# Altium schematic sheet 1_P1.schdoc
size 358 x 309 mm; Symbol: Drawing-Symbol_A4; Device: Drawing-Symbol_A4; @Project Name: esp32_c3_ppm_11_11_2025; @Page Count: 1; @Update Date: 2025-12-08; @Create Date: 2025-12-07; @Schematic Name: Schematic1; @Page No: 1; @Page Name: P1; Company: EasyEDA.com; Version: V1.0; Page Size: A4; @Create Time: 21:49:59; @Update Time: 15:23:27; Width: 1377.9527559055118; Height: 1181.1023622047244; Region Start: 1; X Region Count: 6; Y Region Count: 4; Blade Width: 10; Title Block Position: 3; @Board Name: Board1
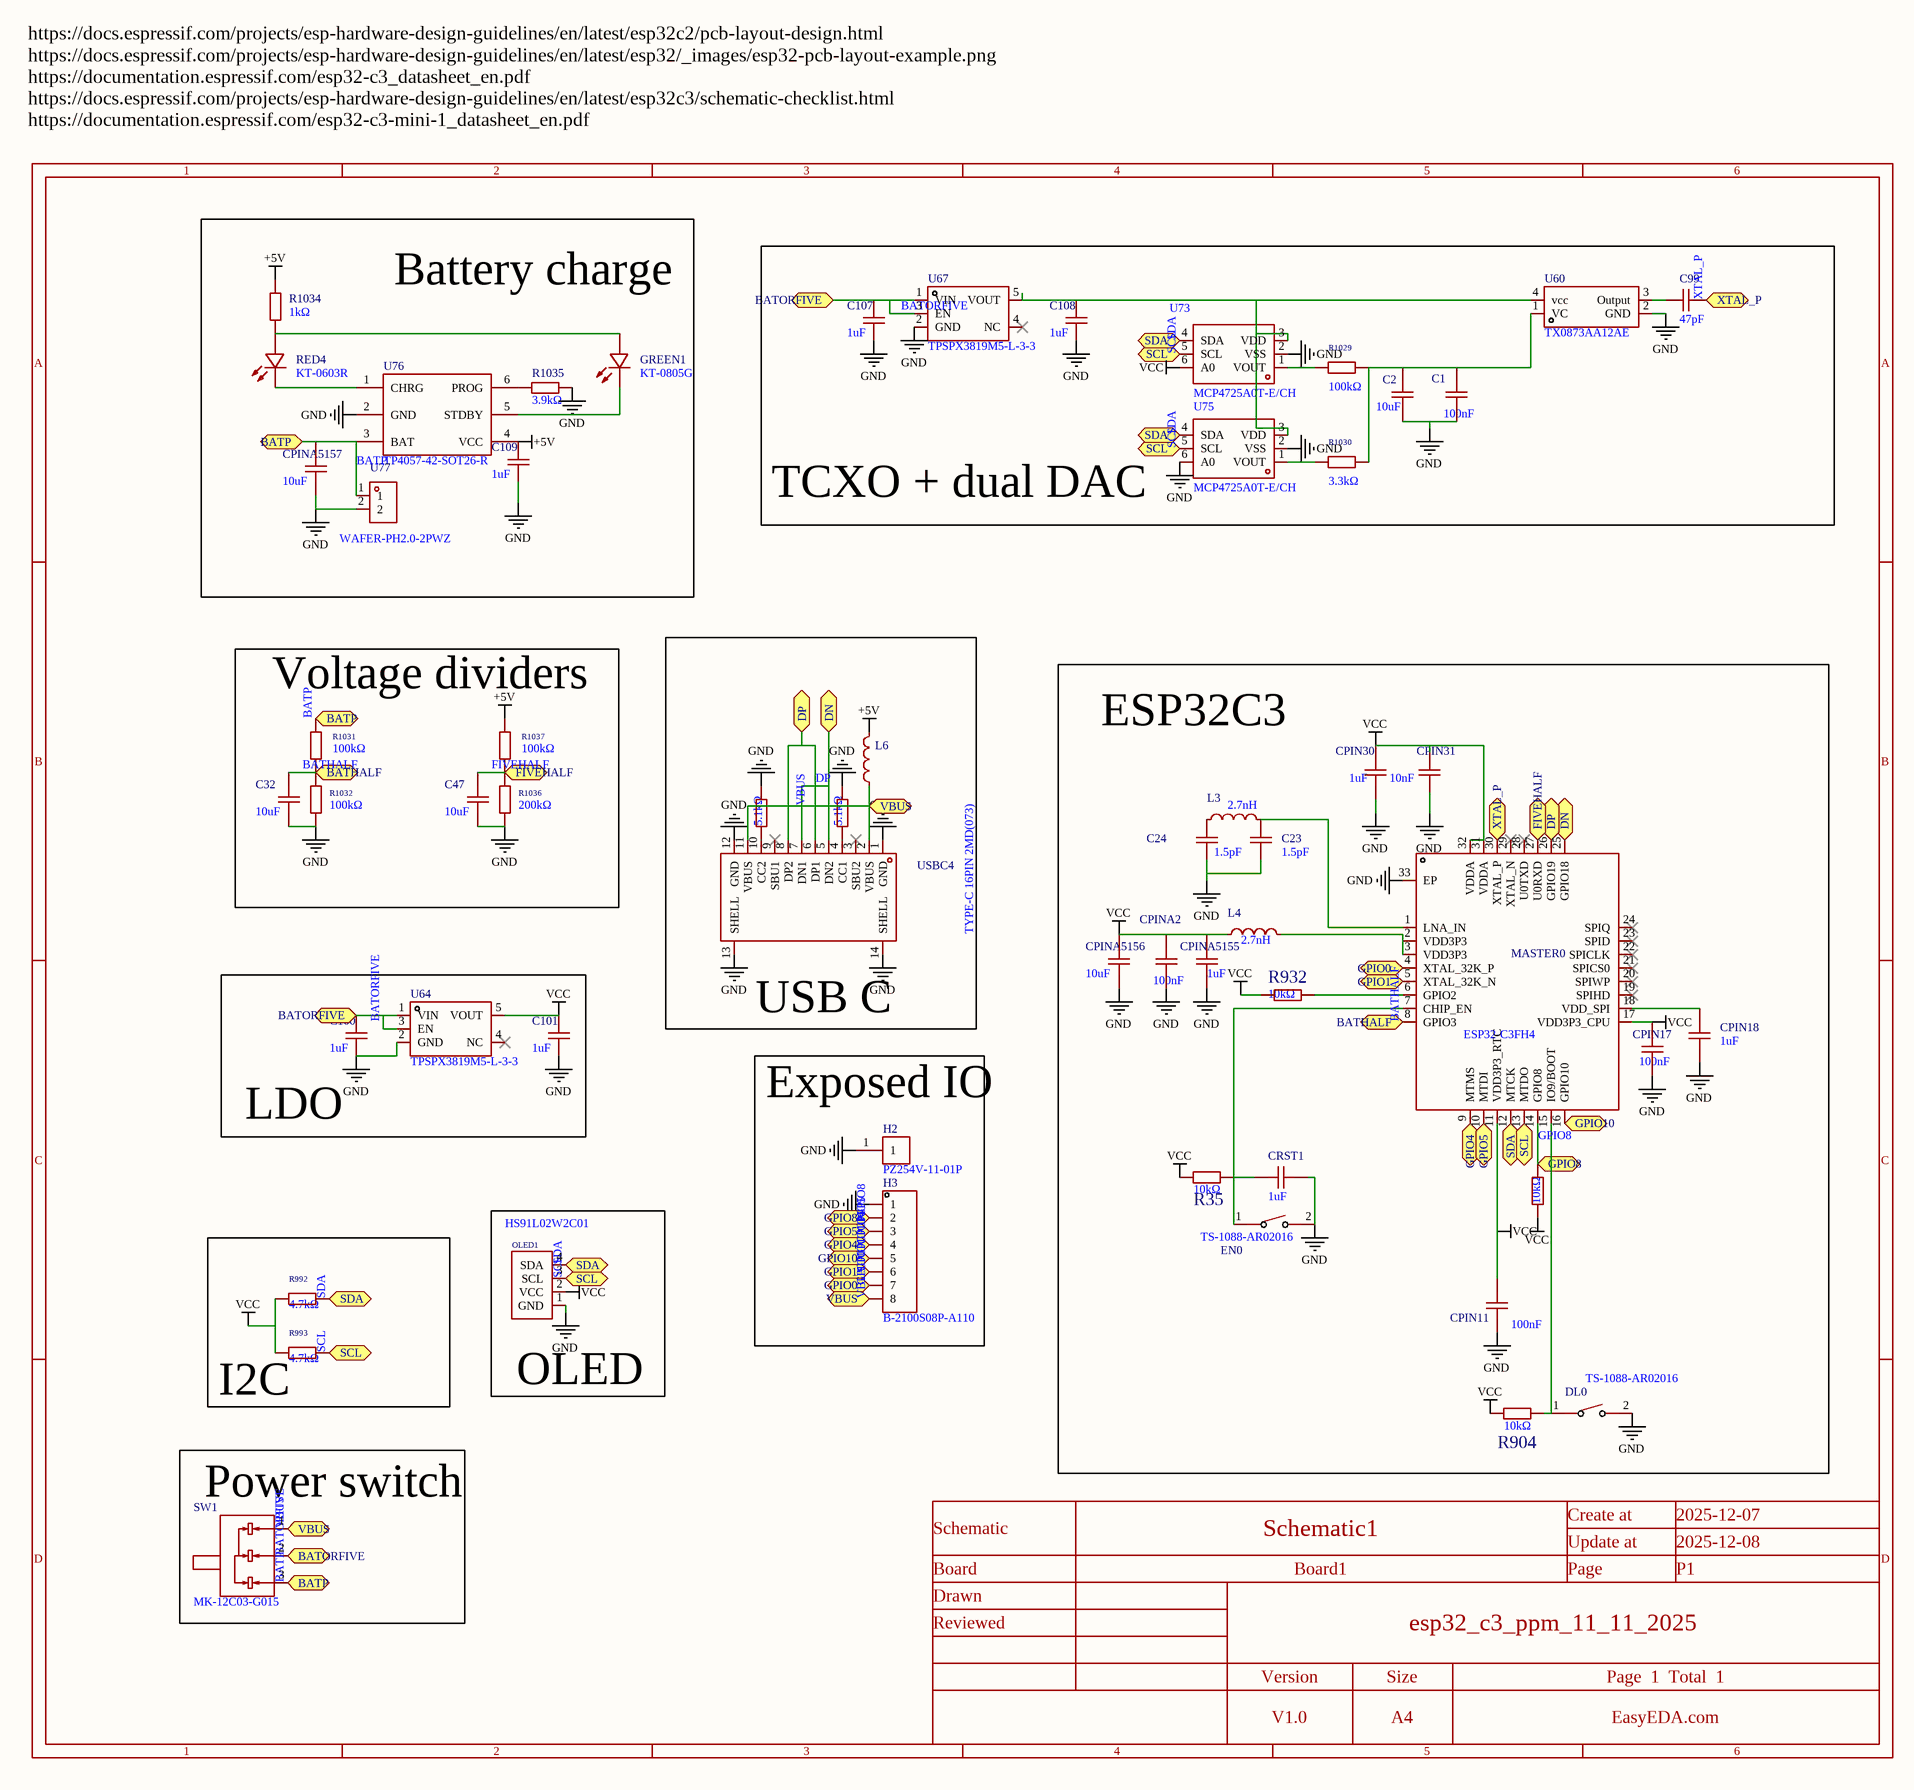
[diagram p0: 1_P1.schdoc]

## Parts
C1  100nF  [C0402]
C2  10uF  [C0402]
C23  1.5pF  [C0402]
C24  1.5pF  [C0402]
C32  10uF  [C0402]
C47  10uF  [C0402]
C99  47pF  [C0402]
C100  1uF  [C0402]
C101  1uF  [C0402]
C107  1uF  [C0402]
C108  1uF  [C0402]
C109  1uF  [C0402]
CPIN11  100nF  [C0402]
CPIN17  100nF  [C0402]
CPIN18  1uF  [C0402]
CPIN30  1uF  [C0402]
CPIN31  10nF  [C0402]
CPINA2  100nF  [C0402]
CPINA5155  1uF  [C0402]
CPINA5156  10uF  [C0402]
CPINA5157  10uF  [C0402]
CRST1  1uF  [C0402]
DL0  TS-1088-AR02016  [SW-SMD_L3.9-W3.0-P4.45]
EN0  TS-1088-AR02016  [SW-SMD_L3.9-W3.0-P4.45]
GREEN1  KT-0805G  [LED0805-R-RD]
H2  PZ254V-11-01P  [HDR-TH_1P-P2.54-V-M]
H3  B-2100S08P-A110  [HDR-TH_8P-P2.54-V-M]
L3  2.7nH  [L0402]
L4  2.7nH  [L0402]
L6  BLM18PG121SN1D  [L0603]  (value not drawn)
MASTER0  ESP32-C3FH4  [QFN-32_L5.0-W5.0-P0.50-TL-EP3.7]
OLED1  HS91L02W2C01  [OLED-TH_L38.0-W12.0_HS91L02W2C01]
R35  10kΩ  [R0402]
R904  10kΩ  [R0402]
R932  10kΩ  [R0402]
R953  5.1kΩ  [R0402]
R954  5.1kΩ  [R0402]
R992  4.7kΩ  [R0402]
R993  4.7kΩ  [R0402]
R1029  100kΩ  [R0402]
R1030  3.3kΩ  [R0402]
R1031  100kΩ  [R0402]
R1032  100kΩ  [R0402]
R1033  10kΩ  [R0402]
R1034  1kΩ  [R0402]
R1035  3.9kΩ  [R0603]
R1036  200kΩ  [R0402]
R1037  100kΩ  [R0402]
RED4  KT-0603R  [LED0603-RD]
SW1  MK-12C03-G015  [SW-SMD_MK-12C03-G015]
U60  TX0873AA12AE  [CRYSTAL-SMD_4P-L2.5-W2.0-BL_TX0873AA12AE]
U64  TPSPX3819M5-L-3-3  [SOT-23-5_L3.0-W1.6-P0.95-LS2.8-BR]
U67  TPSPX3819M5-L-3-3  [SOT-23-5_L3.0-W1.6-P0.95-LS2.8-BR]
U73  MCP4725A0T-E/CH  [SOT-23-6_L2.9-W1.6-P0.95-LS2.8-BL]
U75  MCP4725A0T-E/CH  [SOT-23-6_L2.9-W1.6-P0.95-LS2.8-BL]
U76  TP4057-42-SOT26-R  [SOT-23-6_L2.9-W1.6-P0.95-LS2.8-BL]
U77  WAFER-PH2.0-2PWZ  [CONN-TH_2P-P2.00_GP01-2001WR-2P]
USBC4  TYPE-C 16PIN 2MD(073)  [USB-C-SMD_TYPE-C-6PIN-2MD-073]

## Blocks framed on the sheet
Battery charge: C109 CPINA5157 GREEN1 R1034 R1035 RED4 U76 U77
TCXO + dual DAC: C1 C2 C99 C107 C108 R1029 R1030 U60 U67 U73 U75
Voltage dividers: C32 C47 R1031 R1032 R1036 R1037
USB C: L6 R953 R954 USBC4
ESP32C3: C23 C24 CPIN11 CPIN17 CPIN18 CPIN30 CPIN31 CPINA2 CPINA5155 CPINA5156 CRST1 DL0 EN0 L3 L4 MASTER0 R35 R904 R932 R1033
LDO: C100 C101 U64
Exposed IO: H2 H3
OLED: OLED1
I2C: R992 R993
Power switch: SW1

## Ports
BATHALF (bidir), BATORFIVE (bidir), BATP (bidir), DN (bidir), DP (bidir), FIVEHALF (bidir), GPIO0 (bidir), GPIO1 (bidir), GPIO4 (bidir), GPIO5 (bidir), GPIO8 (bidir), GPIO10 (bidir), SCL (bidir), SDA (bidir), VBUS (bidir), XTAL_P (bidir)

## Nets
+5V: C109.2 L6.2 R1034.1 R1037.2 U76.4(VCC)
GND: C1.1 C2.1 C23.1 C24.1 C32.1 C47.1 C100.1 C101.1 C107.1 C108.1 C109.1 CPIN11.1 CPIN17.1 CPIN18.2 CPIN30.1 CPIN31.1 CPINA2.1 CPINA5155.1 CPINA5156.1 CPINA5157.1 CRST1.1 DL0.2 EN0.2 H2.1 H3.1 MASTER0.33(EP) OLED1.1(GND) R953.1 R954.1 R1032.1 R1035.2 R1036.1 U60.2(GND) U64.2(GND) U67.2(GND) U73.2(VSS) U75.2(VSS) U75.6(A0) U76.2(GND) U77.2 USBC4.1(GND) USBC4.12(GND) USBC4.13(SHELL) USBC4.14(SHELL)
VCC: C101.2 CPIN11.2 CPIN17.2 CPIN30.2 CPIN31.2 CPINA2.2 CPINA5155.2 CPINA5156.2 L4.1 MASTER0.11(VDD3P3_RTC) MASTER0.17(VDD3P3_CPU) MASTER0.31(VDDA) MASTER0.32(VDDA) OLED1.2(VCC) R35.1 R904.1 R932.1 R992.1 R993.1 R1033.1 U64.5(VOUT) U73.6(A0)
BATHALF: C32.2 MASTER0.8(GPIO3) R1031.1 R1032.2 ; port BATHALF
BATORFIVE: C100.2 C107.2 SW1.2 U64.1(VIN) U64.3(EN) U67.1(VIN) U67.3(EN) ; port BATORFIVE
BATP: CPINA5157.2 R1031.2 SW1.3 U76.3(BAT) U77.1 ; port BATP
DP: MASTER0.25(GPIO18) MASTER0.26(GPIO19) USBC4.5(DN2) USBC4.6(DP1) USBC4.7(DN1) USBC4.8(DP2) ; port DP, port DN
FIVEHALF: C47.2 MASTER0.27(U0RXD) R1036.2 R1037.1 ; port FIVEHALF
GPIO0: H3.7 MASTER0.4(XTAL_32K_P) ; port GPIO0
GPIO1: H3.6 MASTER0.5(XTAL_32K_N) ; port GPIO1
GPIO4: H3.4 MASTER0.9(MTMS) ; port GPIO4
GPIO5: H3.3 MASTER0.10(MTDI) ; port GPIO5
GPIO8: H3.2 MASTER0.14(GPIO8) R1033.2 ; port GPIO8
GPIO10: H3.5 MASTER0.16(GPIO10) ; port GPIO10
SCL: MASTER0.13(MTDO) OLED1.3(SCL) R993.2 U73.5(SCL) U75.5(SCL) ; port SCL
SDA: MASTER0.12(MTCK) OLED1.4(SDA) R992.2 U73.4(SDA) U75.4(SDA) ; port SDA
VBUS: H3.8 L6.1 SW1.1 USBC4.2(VBUS) USBC4.11(VBUS) ; port VBUS
XTAL_P: C99.2 MASTER0.30(XTAL_P) ; port XTAL_P
NetC1_2: C1.2 C2.2 R1029.2 R1030.2 U60.1(VC)
NetC23_2: C23.2 L3.2 MASTER0.1(LNA_IN)
NetC24_2: C24.2 L3.1
NetC99_1: C99.1 U60.3(Output)
NetC108_2: C108.2 U60.4(vcc) U67.5(VOUT) U73.3(VDD) U75.3(VDD)
NetCPIN18_1: CPIN18.1 MASTER0.18(VDD_SPI)
NetCRST1_2: CRST1.2 EN0.1 MASTER0.7(CHIP_EN) R35.2
NetDL0_1: DL0.1 MASTER0.15(IO9/BOOT) R904.2
NetGREEN1_1: GREEN1.1(A) R1034.2 RED4.2(A)
NetGREEN1_2: GREEN1.2(K) U76.5(STDBY)
NetL4_2: L4.2 MASTER0.2(VDD3P3) MASTER0.3(VDD3P3)
NetMASTER0_6: MASTER0.6(GPIO2) R932.2
NetR953_2: R953.2 USBC4.4(CC1)
NetR954_2: R954.2 USBC4.10(CC2)
NetR1029_1: R1029.1 U73.1(VOUT)
NetR1030_1: R1030.1 U75.1(VOUT)
NetR1035_1: R1035.1 U76.6(PROG)
NetRED4_1: RED4.1(K) U76.1(CHRG)

Not connected (* = marked no-connect by the designer): MASTER0 19(SPIHD)* 20(SPIWP)* 21(SPICS0)* 22(SPICLK)* 23(SPID)* 24(SPIQ)* 28(U0TXD)* 29(XTAL_N)*; U64 4(NC)*; U67 4(NC)*; USBC4 3(SBU2)* 9(SBU1)*

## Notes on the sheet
- https://docs.espressif.com/projects/esp-hardware-design-guidelines/en/latest/esp32c2/pcb-layout-design.html
  https://docs.espressif.com/projects/esp-hardware-design-guidelines/en/latest/esp32/_images/esp32-pcb-layout-example.png
  https://documentation.espressif.com/esp32-c3_datasheet_en.pdf
  https://docs.espressif.com/projects/esp-hardware-design-guidelines/en/latest/esp32c3/schematic-checklist.html
  https://documentation.espressif.com/esp32-c3-mini-1_datasheet_en.pdf

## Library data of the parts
C1 CPIN11 CPIN17 CPINA2 = CL05B104KB54PNC: Manufacturer: SAMSUNG(三星); Symbol: CC0603KRX7R9BB104; Add into BOM: yes; Tolerance: ±10%
C2 C32 C47 CPINA5156 CPINA5157 = CL05A106MQ5NUNC: Manufacturer: SAMSUNG(三星); Symbol: CL21A106KAYNNNE; Add into BOM: yes; Tolerance: ±20%
C23 C24 = GJM1555C1H1R5WB01D: Manufacturer: muRata(村田); Symbol: 0402CG3R3C500NT; Add into BOM: yes; Voltage Rating: 50V
C99 = 0402CG470J500NT: Manufacturer: FH(风华); Add into BOM: yes; Tolerance: ±5%; Voltage Rating: 50V; Temperature Coefficient: C0G
C100 C101 C107-C109 = CL05A105KA5NQNC: Manufacturer: SAMSUNG(三星); Symbol: CL05A106MQ5NUNC; Add into BOM: yes; Tolerance: ±10%; Temperature Coefficient: X5R; Voltage Rating: 25V
CPIN18 CPIN30 CPINA5155 CRST1 = CL05A105KA5NQNC: Manufacturer: SAMSUNG(三星); Add into BOM: yes; Tolerance: ±10%
CPIN31 = CL05B103KB5NNNC: Manufacturer: SAMSUNG(三星); Add into BOM: yes; Tolerance: ±10%
DL0 EN0 = TS-1088-AR02016: Manufacturer: XUNPU(讯普); Add into BOM: yes; Circuit: SPST; Actuator Style: Round Button; Operating Force: 160gf; Switch Length: 4mm; Switch Width: 3mm; Switch Height: 2mm; Strike Gundam: 不带; Contact Current: 50mA; Voltage Rating (DC): 12V; Insulation Resistance: 100MΩ; Actuator/Cap Color: Black; Pin Style: SMDSplicing; Mechanical Life: 10万次
GREEN1 = KT-0805G: Manufacturer: KENTO; Symbol: 0805G (Green); Add into BOM: yes; Illumination Color: Emerald Green; Voltage - Forward(Vf): 2.6V~3.1V; Power(Watts): 100mW; Forward Current: 5mA; Wavelength - Dominant: 513nm~528nm; Peak Wavelength: 525nm; Luminous Intensity: 430mcd; Viewing Angle: 120°
H2 = PZ254V-11-01P: Manufacturer: XFCN(兴飞); Add into BOM: yes; Pin Structure: 1x1P; Pitch: 2.54mm; Circluar Pins/Square Pins: Pin Header
H3 = B-2100S08P-A110: Manufacturer: Ckmtw(灿科盟); Symbol: Header-Male-2.54_1x8; Add into BOM: yes; Pin Structure: 1x8P; Pitch: 2.54mm
L3 L4 = LQG15HS2N7S02D: Manufacturer: muRata(村田); Add into BOM: yes; Current Rating: 800mA; DC Resistance(DCR): 120mΩ; Q @ Frequency: 8@100MHz; Frequency - Self Resonant: 6GHz
L6 = BLM18PG121SN1D_C14709: Manufacturer: muRata(村田); Add into BOM: yes; Impedance @ Frequency: 120Ω@100MHz; Tolerance: ±25%; DC Resistance(DCR): 50mΩ; Current Rating: 2A; Number of Circuits: 1
MASTER0 = ESP32-C3FH4 COPY: Manufacturer: ESPRESSIF(乐鑫); Convert to PCB: yes
OLED1 = HS91L02W2C01: Manufacturer: HS(汉昇); Add into BOM: yes; Main Control Chip: SSD1306; Interface Type: I2C; Pixel Resolution: 128x32
R35 R904 R932 R1033 = 0402WGF1002TCE: Manufacturer: UNI-ROYAL(厚声); Symbol: 0603WAF1002T5E; Add into BOM: yes; Tolerance: ±1%; Temperature Coefficient: ±100ppm/℃
R953 R954 = 0402WGF5101TCE: Manufacturer: UNI-ROYAL(厚声); Symbol: 0603WAF5101T5E; Add into BOM: yes; Tolerance: ±1%; Power(Watts): 62.5mW; Voltage-Supply(Max): 50V; Temperature Coefficient: ±100ppm/℃
R992 R993 = 0402WGF4701TCE: Manufacturer: UNI-ROYAL(厚声); Add into BOM: yes; Tolerance: ±1%; Power(Watts): 62.5mW; Voltage-Supply(Max): 50V; Temperature Coefficient: ±100ppm/℃
R1029 R1031 R1032 R1037 = 0402WGF1003TCE: Manufacturer: UNI-ROYAL(厚声); Add into BOM: yes; Tolerance: ±1%; Power(Watts): 62.5mW; Voltage-Supply(Max): 50V; Temperature Coefficient: ±100ppm/℃
R1030 = 0402WGF3301TCE: Manufacturer: UNI-ROYAL(厚声); Add into BOM: yes; Tolerance: ±1%; Power(Watts): 62.5mW; Voltage-Supply(Max): 50V; Temperature Coefficient: ±100ppm/℃
R1034 = 0402WGF1001TCE: Manufacturer: UNI-ROYAL(厚声); Add into BOM: yes; Tolerance: ±1%; Power(Watts): 62.5mW; Voltage-Supply(Max): 50V; Temperature Coefficient: ±100ppm/℃
R1035 = 0603WAF3901T5E: Manufacturer: UNI-ROYAL(厚声); Add into BOM: yes; Tolerance: ±1%; Power(Watts): 100mW; Voltage-Supply(Max): 75V; Temperature Coefficient: ±100ppm/℃
R1036 = 0402WGF2003TCE: Manufacturer: UNI-ROYAL(厚声); Add into BOM: yes; Tolerance: ±1%; Power(Watts): 62.5mW; Voltage-Supply(Max): 50V; Temperature Coefficient: ±100ppm/℃
RED4 = KT-0603R: Manufacturer: KENTO; Add into BOM: yes; Emitted Color: Red
SW1 = MK-12C03-G015: Manufacturer: G-Switch(品赞); Add into BOM: yes; Circuit: SPDT; Actuator Style: Rectangular Columnar; Switch Height: 4.25mm; Actuator Color: White; Current Rating: 500mA; Voltage Rating: 12V; Life: 10,000 Cycles
U60 = TX0873AA12AE: Manufacturer: TST(嘉硕); Add into BOM: yes
U64 U67 = TPSPX3819M5-L-3-3: Manufacturer: TECH PUBLIC(台舟); Add into BOM: yes; Output Type: Fixed; Voltage - Supply: 20V; Output Voltage: 3.3V; Output Current: 500mA; Power Supply Rejection Ratio (PSRR): 70dB@(1kHz); Voltage Dropout: 420mV@(100mA); standby current: 5uA; Output Configuration: Positive; Number of Outputs: 1
U73 U75 = MCP4725A0T-E/CH: Manufacturer: MICROCHIP(美国微芯); Add into BOM: yes; Resolution(Bits): 12Bit; Number of Channels: 1; Interface: I2C; Voltage - Supply: 2.7V~5.5V; Settling Time: 6us; INL/DNL(LSB): 2LSB
U76 = TP4057-42-SOT26-R: Manufacturer: TOPPOWER(南京拓微); Symbol: TP4057; Add into BOM: yes
U77 = WAFER-PH2.0-2PWZ: Manufacturer: XUNPU(讯普); Add into BOM: yes; Pins Structure: 1x2P; Pitch: 2mm; Reference Series: PH; Number of PINs Per Row: 2; Current Rating: 2A; Voltage Rating: 250V; Plastic Material: PA66; Flame Retardant Rating: UL94V-0; Z-Height of the Board: 4.7mm; X-Length of Bottom Edge on Board (Spacing Line): 6mm; Y-Width of Bottom Edge on Board: 6.05mm
USBC4 = TYPE-C 16PIN 2MD(073): Manufacturer: SHOU HAN(首韩); Add into BOM: yes; Gender: Female; Number of Contacts: 16P; Number of Ports: 1; Current Rating - Power (Max): 5A; Rated Voltage (Max): 5V; Connect-Disconnect Life: 5,000 Cycles; Core Colour: Black; Protocol Standard: USB 3.1; Current Rating-Power: 3A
